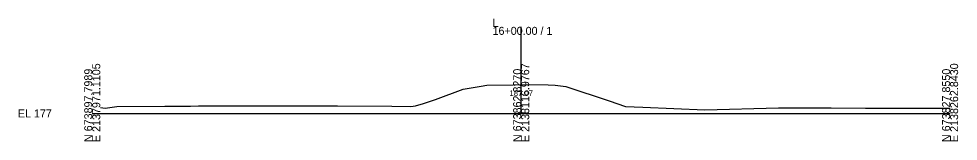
# Model space of a CAD drawing. Extents: x -26 to 5503, y -10 to 7033.
# Drawn here: x -25.7 to 302.8, y 6990.3 to 7033 of the extents above; entities that cross this region are included whole.
import ezdxf

# ---------------------------------------------------------------- set-up
doc = ezdxf.new("R2010")
doc.units = 0
for name, color, linetype in [('Exist Cross Section Cell', 7, 'Continuous'), ('Exist XS Center Line Elevation Label', 7, 'Continuous'), ('Exist XS Ground Line', 7, 'Continuous')]:
    doc.layers.add(name, color=color, linetype=linetype)

msp = doc.modelspace()

# ---------------------------------------------------------------- linework, layer by layer
at = {"layer": 'Exist Cross Section Cell'}
for p, q in [((150, 7000), (150, 7030.22)), ((0, 7000), (150, 7000)), ((150, 7000), (300, 7000))]:
    msp.add_line(p, q, dxfattribs=at)
at = {"layer": 'Exist XS Ground Line'}
for p, q in [((119.99, 7004.89), (129.74, 7008.41)), ((129.74, 7008.41), (136.02, 7009.56)), ((136.02, 7009.56), (137.99, 7009.84)), ((137.99, 7009.84), (147.16, 7010.03)), ((147.16, 7010.03), (149.99, 7010.07)), ((149.99, 7010.07), (159.4, 7009.93)), ((159.4, 7009.93), (161.93, 7009.89)), ((161.93, 7009.89), (162.82, 7009.79)), ((162.82, 7009.79), (165.62, 7009.42)), ((165.62, 7009.42), (180.72, 7004.34)), ((115.82, 7003.45), (119.99, 7004.89)), ((180.72, 7004.34), (186.48, 7002.44)), ((2.83, 7002.03), (4.57, 7001.79)), ((4.57, 7001.79), (8.59, 7002.44)), ((8.59, 7002.44), (25.35, 7002.53)), ((25.35, 7002.53), (34.3, 7002.58)), ((34.3, 7002.58), (37.13, 7002.59)), ((37.13, 7002.59), (60.01, 7002.63)), ((60.01, 7002.63), (70.94, 7002.65)), ((70.94, 7002.65), (85.72, 7002.63)), ((85.72, 7002.63), (104.76, 7002.5)), ((104.76, 7002.5), (111.43, 7002.43)), ((111.43, 7002.43), (113.02, 7002.6)), ((113.02, 7002.6), (115.82, 7003.45)), ((186.48, 7002.44), (192.6, 7002.13)), ((192.6, 7002.13), (214.26, 7001.19)), ((214.26, 7001.19), (240.04, 7001.89)), ((240.04, 7001.89), (258.36, 7001.9)), ((258.36, 7001.9), (270.46, 7001.84)), ((270.46, 7001.84), (282.85, 7001.79)), ((282.85, 7001.79), (291.39, 7001.83)), ((291.39, 7001.83), (300, 7001.86))]:
    msp.add_line(p, q, dxfattribs=at)

# ---------------------------------------------------------------- texts
at = {"layer": 'Exist Cross Section Cell'}
for s, p in [('L', (140, 7030.22)), ('16+00.00 / 1', (140, 7027.42)), ('EL 177', (-26, 6998.6))]:
    msp.add_text(s, height=2.8, dxfattribs=at).set_placement(p)
for s, p in [('N 673897.7989', (0, 6990)), ('E 2137971.1105', (2.8, 6990)), ('N 673862.8270', (150, 6990)), ('E 2138116.9767', (152.8, 6990)), ('N 673827.8550', (300, 6990)), ('E 2138262.8430', (302.8, 6990))]:
    msp.add_text(s, height=2.8, rotation=90, dxfattribs=at).set_placement(p)
at = {"layer": 'Exist XS Center Line Elevation Label'}
msp.add_text('187.07', height=2, dxfattribs=at).set_placement((145.94, 7006.07))

doc.saveas('drawing.dxf')
